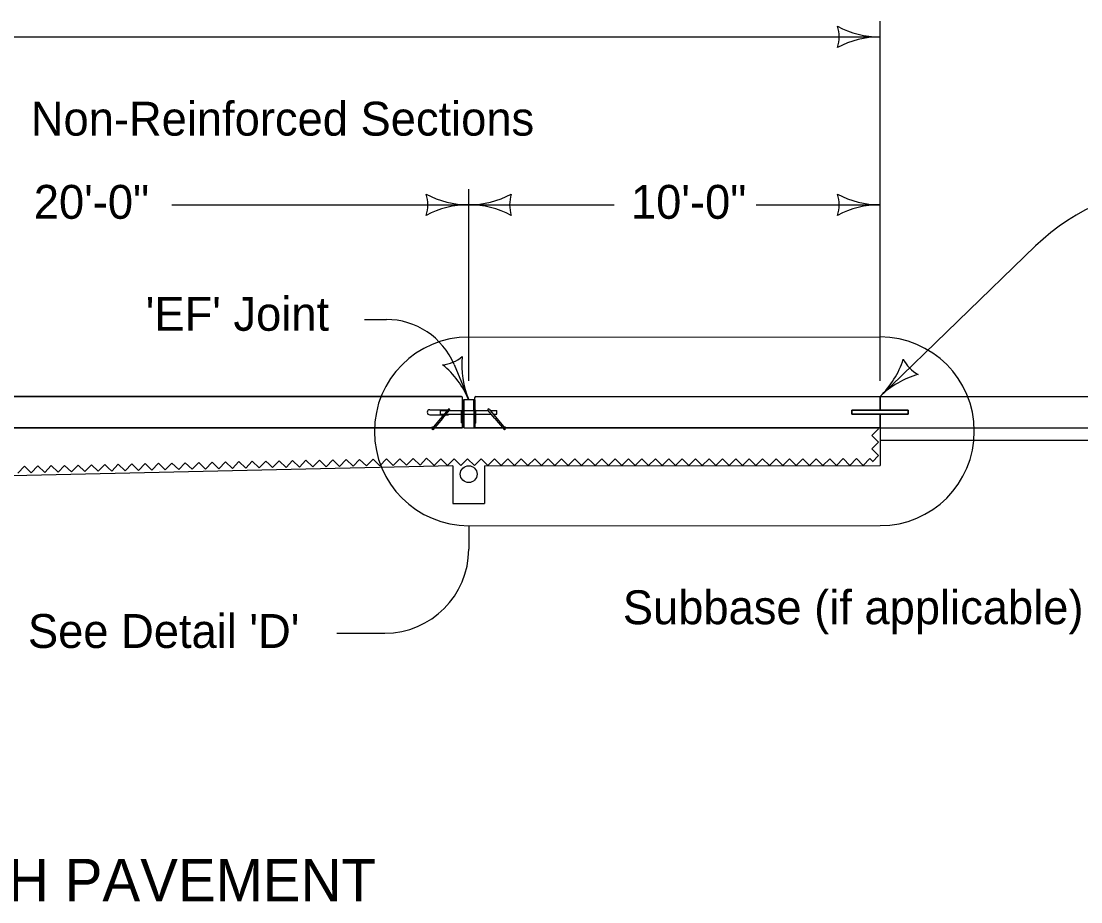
# Model space of a CAD drawing. Extents: x 10130 to 81668, y 5440 to 21644.
# Drawn here: x 14242 to 14743, y 10335 to 10751 of the extents above; entities that cross this region are included whole.
import ezdxf

# ---------------------------------------------------------------- set-up
doc = ezdxf.new("R2010")
doc.units = 0
for name, color, linetype in [('dsnNonPlotable', 7, 'Continuous'), ('dsnStdBlock', 7, 'Continuous'), ('dsnStdBlockModified', 7, 'Continuous'), ('dsnStdBlockNotModified', 7, 'Continuous'), ('dsnStdBorder', 7, 'Continuous')]:
    doc.layers.add(name, color=color, linetype=linetype)

msp = doc.modelspace()

# ---------------------------------------------------------------- linework, layer by layer
at = {"layer": 'dsnNonPlotable'}
for p, q in [((14648, 10581.16), (14648, 10750.92)), ((13295.34, 10743.45), (14648, 10743.49)), ((14453.64, 10581.12), (14453.64, 10671.68)), ((14313.31, 10664.25), (14453.64, 10664.25)), ((14453.64, 10664.25), (14522.41, 10664.25)), ((14589.52, 10664.25), (14648, 10664.25))]:
    msp.add_line(p, q, dxfattribs=at)
for centre, radius, start, end in [((14612.16, 10743.5), 16.51, 342.2666, 17.7333), ((14648, 10786.25), 42.75, 241.9275, 270), ((14648, 10700.75), 42.75, 90, 118.0725), ((14417.8, 10664.26), 16.51, 342.2666, 17.7333), ((14453.64, 10707), 42.75, 241.9275, 270), ((14453.64, 10707), 42.75, 270, 298.0725), ((14489.49, 10664.26), 16.51, 162.2666, 197.7334), ((14612.15, 10664.26), 16.51, 342.2666, 17.7333), ((14648, 10707), 42.75, 241.9275, 270), ((14453.64, 10621.51), 42.75, 90, 118.0725), ((14453.64, 10621.51), 42.75, 61.9275, 90), ((14648, 10621.51), 42.75, 90, 118.0725)]:
    msp.add_arc(centre, radius, start, end, dxfattribs=at)
at = {"layer": 'dsnStdBlock'}
for p, q in [((14450.67, 10572.09), (14451.27, 10572.09)), ((14456.02, 10572.09), (14456.61, 10572.09)), ((14644.66, 10558.89), (14642.74, 10558.89))]:
    msp.add_line(p, q, dxfattribs=at)
for points in [[(14451.27, 10572.04), (14451.31, 10572.09)], [(14644.36, 10542.88), (14647.27, 10545.78), (14644.1, 10548.95), (14647.27, 10552.12), (14644.1, 10555.29), (14647.26, 10558.46), (14646.83, 10558.89)], [(14359.36, 10541.69), (14360.97, 10540.14), (14364.08, 10543.36), (14367.31, 10540.25), (14370.42, 10543.47), (14373.64, 10540.36), (14376.75, 10543.58), (14379.98, 10540.47), (14383.09, 10543.69), (14386.31, 10540.58), (14389.42, 10543.8), (14392.65, 10540.69), (14395.76, 10543.91), (14398.98, 10540.8), (14402.09, 10544.02), (14405.32, 10540.91), (14408.43, 10544.13), (14411.65, 10541.02), (14414.76, 10544.24), (14417.99, 10541.13), (14421.1, 10544.35), (14424.32, 10541.24), (14427.43, 10544.46), (14430.66, 10541.35), (14433.77, 10544.58), (14435.7, 10542.7)], [(14435.7, 10542.7), (14437.29, 10541.12), (14440.46, 10544.29), (14443.62, 10541.12), (14446.79, 10544.29), (14449.96, 10541.12), (14453.13, 10544.29), (14456.3, 10541.12), (14459.46, 10544.29), (14462.63, 10541.13), (14465.8, 10544.3), (14468.97, 10541.13), (14472.14, 10544.3), (14475.3, 10541.13), (14478.47, 10544.3), (14481.64, 10541.14), (14484.81, 10544.3), (14487.98, 10541.14), (14491.14, 10544.3), (14494.31, 10541.14), (14497.48, 10544.31), (14500.65, 10541.14), (14503.82, 10544.31), (14506.98, 10541.14), (14510.15, 10544.31), (14511.74, 10542.73)], [(14511.74, 10542.73), (14513.32, 10541.14), (14516.49, 10544.32), (14519.66, 10541.15), (14522.82, 10544.32), (14525.99, 10541.15), (14529.16, 10544.32), (14532.33, 10541.15), (14535.5, 10544.32), (14538.66, 10541.16), (14541.83, 10544.32), (14545, 10541.16), (14548.17, 10544.32), (14551.34, 10541.16), (14554.5, 10544.33), (14557.67, 10541.16), (14560.84, 10544.33), (14564.01, 10541.16), (14567.18, 10544.33), (14570.34, 10541.16), (14573.51, 10544.34), (14576.68, 10541.17), (14579.85, 10544.34), (14583.02, 10541.17), (14586.18, 10544.34), (14587.77, 10542.76)], [(14587.77, 10542.76), (14589.35, 10541.17), (14592.52, 10544.35), (14595.69, 10541.18), (14598.86, 10544.35), (14602.02, 10541.18), (14605.19, 10544.35), (14608.36, 10541.18), (14611.53, 10544.35), (14614.7, 10541.18), (14617.86, 10544.35), (14621.03, 10541.18), (14624.2, 10544.35), (14627.37, 10541.19), (14630.54, 10544.36), (14633.7, 10541.19), (14636.87, 10544.36), (14640.04, 10541.19), (14643.21, 10544.36), (14644.53, 10543.04)], [(14240.62, 10537.57), (14243.72, 10540.8), (14246.95, 10537.7), (14250.05, 10540.94), (14253.28, 10537.84), (14256.38, 10541.07), (14259.62, 10537.97), (14262.72, 10541.21), (14265.95, 10538.11), (14269.05, 10541.35), (14272.29, 10538.24), (14275.39, 10541.48), (14278.62, 10538.38), (14281.72, 10541.62), (14283.34, 10540.07)], [(14283.34, 10540.07), (14284.96, 10538.52), (14288.06, 10541.75), (14291.29, 10538.65), (14294.39, 10541.89), (14297.63, 10538.79), (14300.72, 10542.02), (14303.96, 10538.92), (14307.06, 10542.16), (14310.29, 10539.06), (14313.4, 10542.29), (14316.63, 10539.19), (14319.73, 10542.43), (14322.96, 10539.33), (14326.06, 10542.57), (14329.3, 10539.46), (14332.4, 10542.7), (14335.64, 10539.6), (14338.73, 10542.84), (14341.97, 10539.74), (14345.07, 10542.97), (14348.3, 10539.87), (14351.4, 10543.11), (14354.64, 10540.01), (14357.74, 10543.24), (14359.36, 10541.69)]]:
    msp.add_lwpolyline(points, dxfattribs=at)
at = {"layer": 'dsnStdBlockModified'}
for p, q in [((14456.61, 10573.28), (14456.61, 10573.28)), ((14456.61, 10558.84), (14456.61, 10573.28)), ((14457.03, 10573.69), (14648, 10573.74)), ((14648, 10573.74), (14648, 10573.78)), ((14648, 10573.78), (14648, 10567.28)), ((14648, 10573.74), (14648, 10567.25)), ((14648, 10567.25), (14648, 10573.74)), ((14648, 10567.28), (14634.63, 10567.28)), ((14634.63, 10567.28), (14634.63, 10565.42)), ((14648, 10567.25), (14634.63, 10567.24)), ((14634.63, 10567.24), (14648, 10567.25)), ((14634.63, 10567.24), (14634.63, 10565.38)), ((14661.36, 10567.24), (14634.63, 10567.24)), ((14634.63, 10565.43), (14648, 10565.43)), ((14634.63, 10565.38), (14647.98, 10565.38)), ((14647.98, 10565.38), (14648, 10558.89)), ((14648, 10558.89), (14647.98, 10565.38)), ((14648, 10565.43), (14648, 10558.93)), ((14648, 10565.35), (14661.36, 10565.38)), ((14661.36, 10565.38), (14661.36, 10567.24)), ((14544.21, 10558.84), (14456.61, 10558.84)), ((14648, 10558.89), (14544.21, 10558.84)), ((14648, 10558.93), (14648, 10558.89))]:
    msp.add_line(p, q, dxfattribs=at)
msp.add_lwpolyline([(14456.61, 10573.28), (14456.7, 10573.62), (14457.03, 10573.69)], dxfattribs=at)
at = {"layer": 'dsnStdBlockNotModified'}
for p, q in [((14648, 10573.74), (14721.45, 10644.79)), ((14404.37, 10610.09), (14414.72, 10610.09)), ((14453.64, 10601.79), (14648, 10601.83)), ((14446.71, 10588.75), (14453.64, 10572.09)), ((14453.64, 10512.69), (14648, 10512.73)), ((14453.64, 10512.69), (14453.64, 10501.59)), ((14391.4, 10461.99), (14414.04, 10461.99))]:
    msp.add_line(p, q, dxfattribs=at)
for centre, radius, start, end in [((14790.98, 10572.92), 100, 90, 134.0496), ((14414.72, 10575.44), 34.65, 22.5907, 90), ((14453.64, 10557.24), 44.55, 90, 270), ((14648, 10557.28), 44.55, 270, 90), ((14439.87, 10605.18), 16.51, 274.8585, 310.3252), ((14493.11, 10588.51), 42.75, 174.5193, 202.5918), ((14618.28, 10604.46), 42.75, 314.0498, 342.1223), ((14673.76, 10598.66), 16.51, 206.3164, 241.7831), ((14414.18, 10555.67), 42.75, 22.5918, 50.6643), ((14677.72, 10543.01), 42.75, 105.9773, 134.0498), ((14414.04, 10501.59), 39.6, 270, 360)]:
    msp.add_arc(centre, radius, start, end, dxfattribs=at)
at = {"layer": 'dsnStdBorder'}
for p, q in [((13295.34, 10573.69), (14450.25, 10573.69)), ((14450.25, 10573.69), (14097.24, 10573.69)), ((14450.67, 10567.18), (14450.67, 10573.28)), ((14450.67, 10563.36), (14450.67, 10573.28)), ((14450.73, 10572.09), (14450.73, 10563.36)), ((14450.79, 10572.09), (14450.79, 10563.36)), ((14450.85, 10572.09), (14450.85, 10563.36)), ((14450.91, 10572.09), (14450.91, 10563.36)), ((14450.97, 10572.09), (14450.97, 10563.36)), ((14451.03, 10572.09), (14451.03, 10563.36)), ((14451.08, 10572.09), (14451.08, 10563.36)), ((14451.15, 10572.09), (14451.15, 10563.36)), ((14451.2, 10572.09), (14451.2, 10563.36)), ((14451.27, 10572.09), (14451.27, 10567.16)), ((14456.02, 10572.09), (14451.27, 10572.09)), ((14451.27, 10572.09), (14451.27, 10567.16)), ((14456.02, 10572.09), (14456.02, 10567.16)), ((14456.02, 10567.16), (14456.02, 10572.09)), ((14456.07, 10572.09), (14456.07, 10563.36)), ((14456.14, 10572.09), (14456.14, 10563.36)), ((14456.19, 10572.09), (14456.19, 10563.36)), ((14456.26, 10572.09), (14456.26, 10563.36)), ((14456.31, 10572.09), (14456.31, 10563.36)), ((14456.38, 10572.09), (14456.38, 10563.36)), ((14456.43, 10572.09), (14456.43, 10563.36)), ((14456.49, 10572.09), (14456.49, 10563.36)), ((14456.55, 10572.09), (14456.55, 10563.36)), ((14456.61, 10563.36), (14456.61, 10573.28)), ((14457.02, 10573.69), (14648, 10573.74)), ((14648, 10573.74), (14648, 10567.24)), ((14648, 10573.74), (14794.18, 10573.74)), ((14435.23, 10567.46), (14443.79, 10567.46)), ((14435.23, 10565.08), (14441.8, 10565.08)), ((14440.27, 10565.38), (14440.27, 10567.16)), ((14440.27, 10567.16), (14443.55, 10567.16)), ((14440.27, 10565.38), (14442.05, 10565.38)), ((14444.04, 10567.75), (14440.35, 10563.36)), ((14441.28, 10563.36), (14444.58, 10567.29)), ((14442.73, 10565.08), (14444.14, 10565.08)), ((14442.98, 10565.38), (14450.32, 10565.38)), ((14443.55, 10567.16), (14443.55, 10567.16)), ((14444.14, 10565.38), (14444.14, 10565.08)), ((14444.47, 10567.16), (14450.32, 10567.16)), ((14450.31, 10561.22), (14450.31, 10567.16)), ((14450.32, 10561.22), (14450.32, 10567.16)), ((14450.49, 10567.34), (14450.49, 10567.34)), ((14451.27, 10567.16), (14451.27, 10565.38)), ((14451.27, 10567.16), (14456.02, 10567.16)), ((14451.27, 10565.38), (14456.02, 10565.38)), ((14451.27, 10565.38), (14451.27, 10563.36)), ((14456.02, 10567.16), (14456.02, 10565.38)), ((14456.02, 10565.38), (14456.02, 10563.36)), ((14456.97, 10561.22), (14456.97, 10567.16)), ((14456.97, 10567.16), (14462.81, 10567.16)), ((14456.97, 10566.92), (14456.97, 10566.92)), ((14456.97, 10565.38), (14464.3, 10565.38)), ((14466, 10563.36), (14462.7, 10567.29)), ((14463.25, 10567.75), (14466.93, 10563.36)), ((14463.74, 10567.16), (14463.74, 10567.16)), ((14463.74, 10567.16), (14467, 10567.16)), ((14465.23, 10565.38), (14467, 10565.38)), ((14467, 10565.38), (14467, 10567.16)), ((14634.63, 10565.38), (14634.63, 10567.24)), ((14634.63, 10567.24), (14661.36, 10567.24)), ((14661.36, 10565.38), (14634.63, 10565.38)), ((14648, 10565.38), (14648, 10558.89)), ((14661.36, 10567.24), (14661.36, 10565.38)), ((14438.6, 10561.27), (14436.19, 10558.39)), ((14439.53, 10561.27), (14436.73, 10557.93)), ((14440.35, 10563.36), (14438.6, 10561.27)), ((14441.28, 10563.36), (14439.53, 10561.27)), ((14450.32, 10561.22), (14450.32, 10561.22)), ((14450.67, 10561.27), (14450.67, 10563.36)), ((14450.67, 10558.84), (14450.67, 10561.27)), ((14450.67, 10558.84), (14450.67, 10561.22)), ((14450.73, 10563.36), (14450.73, 10561.27)), ((14450.73, 10561.27), (14450.73, 10558.84)), ((14450.79, 10563.36), (14450.79, 10561.27)), ((14450.79, 10561.27), (14450.79, 10558.84)), ((14450.85, 10563.36), (14450.85, 10561.27)), ((14450.85, 10561.27), (14450.85, 10558.84)), ((14450.91, 10563.36), (14450.91, 10561.27)), ((14450.91, 10561.27), (14450.91, 10558.84)), ((14450.97, 10563.36), (14450.97, 10561.27)), ((14450.97, 10561.27), (14450.97, 10558.84)), ((14451.03, 10563.36), (14451.03, 10561.27)), ((14451.03, 10561.27), (14451.03, 10558.84)), ((14451.08, 10563.36), (14451.08, 10561.27)), ((14451.08, 10561.27), (14451.08, 10558.84)), ((14451.15, 10563.36), (14451.15, 10561.27)), ((14451.15, 10561.27), (14451.15, 10558.84)), ((14451.2, 10563.36), (14451.2, 10561.27)), ((14451.2, 10561.27), (14451.2, 10558.84)), ((14451.27, 10563.36), (14451.27, 10561.27)), ((14451.27, 10561.27), (14451.27, 10558.84)), ((14456.02, 10563.36), (14456.02, 10561.27)), ((14456.02, 10561.27), (14456.02, 10558.84)), ((14456.07, 10563.36), (14456.07, 10561.27)), ((14456.07, 10561.27), (14456.07, 10558.84)), ((14456.14, 10563.36), (14456.14, 10561.27)), ((14456.14, 10561.27), (14456.14, 10558.84)), ((14456.19, 10563.36), (14456.19, 10561.27)), ((14456.19, 10561.27), (14456.19, 10558.84)), ((14456.26, 10563.36), (14456.26, 10561.27)), ((14456.26, 10561.27), (14456.26, 10558.84)), ((14456.31, 10563.36), (14456.31, 10561.27)), ((14456.31, 10561.27), (14456.31, 10558.84)), ((14456.38, 10563.36), (14456.38, 10561.27)), ((14456.38, 10561.27), (14456.38, 10558.84)), ((14456.43, 10563.36), (14456.43, 10561.27)), ((14456.43, 10561.27), (14456.43, 10558.84)), ((14456.49, 10563.36), (14456.49, 10561.27)), ((14456.49, 10561.27), (14456.49, 10558.84)), ((14456.55, 10563.36), (14456.55, 10561.27)), ((14456.55, 10561.27), (14456.55, 10558.84)), ((14456.61, 10561.27), (14456.61, 10563.36)), ((14456.61, 10558.84), (14456.61, 10561.27)), ((14466, 10563.36), (14467.75, 10561.27)), ((14466.93, 10563.36), (14468.68, 10561.27)), ((14467.75, 10561.27), (14470.55, 10557.93)), ((14468.68, 10561.27), (14471.1, 10558.39)), ((14436.57, 10558.84), (13636.18, 10558.84)), ((14097.24, 10558.84), (14436.56, 10558.84)), ((14436.73, 10557.93), (14436.19, 10558.39)), ((14436.56, 10558.84), (14450.67, 10558.84)), ((14450.67, 10558.84), (14437.49, 10558.84)), ((14451.27, 10558.84), (14456.02, 10558.84)), ((14456.02, 10558.84), (14648, 10558.89)), ((14470.55, 10557.93), (14471.1, 10558.39)), ((14648, 10558.89), (14648, 10541.07)), ((14648, 10558.89), (14794.18, 10558.89)), ((14794.18, 10552.95), (14648, 10552.95)), ((14446.21, 10541.02), (13328.98, 10515.78)), ((14446.21, 10541.02), (14446.21, 10523.2)), ((14461.06, 10541.02), (14648, 10541.07)), ((14461.06, 10541.02), (14461.06, 10523.2)), ((14446.21, 10523.2), (14461.06, 10523.2))]:
    msp.add_line(p, q, dxfattribs=at)
msp.add_lwpolyline([(14451.27, 10565.28), (14451.36, 10565.38)], dxfattribs=at)
for centre, radius in [((14441.29, 10564.84), 0.238), ((14465.75, 10565.14), 0.238), ((14436.46, 10559.08), 0.238), ((14470.83, 10559.08), 0.238), ((14453.64, 10537.06), 3.96)]:
    msp.add_circle(centre, radius, dxfattribs=at)
for centre, radius, start, end in [((14450.25, 10573.28), 0.416, 360, 90), ((14450.26, 10573.28), 0.416, 0, 90), ((14457.03, 10573.28), 0.416, 90, 180), ((14435.23, 10566.27), 1.19, 90, 270), ((14444.31, 10567.52), 0.356, 320.0037, 139.9964), ((14450.49, 10567.16), 0.178, 5.4327, 180), ((14450.5, 10567.16), 0.178, 0, 180), ((14456.79, 10567.16), 0.178, 0, 180), ((14462.98, 10567.52), 0.356, 40.0036, 219.9963), ((14450.49, 10561.22), 0.178, 180, 359.9372), ((14450.5, 10561.22), 0.178, 180, 0), ((14456.79, 10561.22), 0.178, 180, 0)]:
    msp.add_arc(centre, radius, start, end, dxfattribs=at)
for points in [[(14456.97, 10567.04), (14457, 10567.04), (14457.03, 10567.04), (14457.06, 10567.04), (14457.08, 10567.04), (14457.1, 10567.04), (14457.11, 10567.04)], [(14456.97, 10566.92), (14457, 10566.92), (14457.03, 10566.92), (14457.06, 10566.92), (14457.08, 10566.92), (14457.1, 10566.92), (14457.11, 10566.92)], [(14456.97, 10566.8), (14457, 10566.8), (14457.03, 10566.8), (14457.06, 10566.8), (14457.08, 10566.8), (14457.1, 10566.8), (14457.11, 10566.8)], [(14456.97, 10566.68), (14457, 10566.68), (14457.03, 10566.68), (14457.06, 10566.68), (14457.08, 10566.68), (14457.1, 10566.68), (14457.11, 10566.68)], [(14456.97, 10566.57), (14457, 10566.56), (14457.03, 10566.57), (14457.06, 10566.57), (14457.08, 10566.57), (14457.1, 10566.56), (14457.11, 10566.57)], [(14456.97, 10566.45), (14457, 10566.44), (14457.03, 10566.45), (14457.06, 10566.45), (14457.08, 10566.45), (14457.1, 10566.44), (14457.11, 10566.45)], [(14456.97, 10566.33), (14457, 10566.32), (14457.03, 10566.33), (14457.06, 10566.33), (14457.08, 10566.33), (14457.1, 10566.32), (14457.11, 10566.33)], [(14456.97, 10566.21), (14457, 10566.2), (14457.03, 10566.21), (14457.06, 10566.21), (14457.08, 10566.21), (14457.1, 10566.2), (14457.11, 10566.21)], [(14456.97, 10566.09), (14457, 10566.09), (14457.03, 10566.09), (14457.06, 10566.09), (14457.08, 10566.09), (14457.1, 10566.09), (14457.11, 10566.09)], [(14456.97, 10565.97), (14457, 10565.97), (14457.03, 10565.97), (14457.06, 10565.97), (14457.08, 10565.97), (14457.1, 10565.97), (14457.11, 10565.97)], [(14456.97, 10565.85), (14457, 10565.85), (14457.03, 10565.85), (14457.06, 10565.85), (14457.08, 10565.85), (14457.1, 10565.85), (14457.11, 10565.85)], [(14456.97, 10565.73), (14457, 10565.73), (14457.03, 10565.73), (14457.06, 10565.73), (14457.08, 10565.73), (14457.1, 10565.73), (14457.11, 10565.73)], [(14456.97, 10565.61), (14457, 10565.61), (14457.03, 10565.61), (14457.06, 10565.61), (14457.08, 10565.61), (14457.1, 10565.61), (14457.11, 10565.61)], [(14456.97, 10565.5), (14457, 10565.49), (14457.03, 10565.5), (14457.06, 10565.5), (14457.08, 10565.5), (14457.1, 10565.49), (14457.11, 10565.5)]]:
    msp.add_spline(points, degree=3, dxfattribs=at)

# ---------------------------------------------------------------- texts
at = {"layer": 'dsnNonPlotable'}
for s, p in [('Non-Reinforced Sections', (14246.73, 10696.9)), ('20\'-0"', (14248.14, 10657.62)), ('10\'-0"', (14530.31, 10657.62))]:
    msp.add_text(s, height=16, dxfattribs=at).set_placement(p)
at = {"layer": 'dsnStdBlockModified'}
msp.add_text('SECTION THRU CENTERLINE - EAST APPROACH PAVEMENT', height=20, dxfattribs=at).set_placement((13626.72, 10335.4))
at = {"layer": 'dsnStdBlockNotModified'}
for s, p in [("'EF' Joint", (14301.03, 10604.75)), ('Subbase (if applicable)', (14526.47, 10466.19)), ("See Detail 'D'", (14245.37, 10454.98))]:
    msp.add_text(s, height=16, dxfattribs=at).set_placement(p)

doc.saveas('drawing.dxf')
